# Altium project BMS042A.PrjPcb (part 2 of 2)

## Sheet BMS042A_SCH_Hardware.SchDoc
size 431 x 279 mm; Date: Not shown in title block; ApprovedBy: Not shown in title block; CheckedBy: Not shown in title block; Author: Not shown in title block; CompanyName: Not shown in title block; DrawnBy: Pengzhao Zhu; Engineer: Not shown in title block; Organization: Not shown in title block; Address1: Not shown in title block; Address2: Not shown in title block; Address3: Not shown in title block; Address4: Not shown in title block; DocumentNumber: 4; Revision: Use project parameter SCH_Rev; SheetNumber: 4; SheetTotal: 4; PageSetup: Record=PageOptions¦CenterHorizontal=True¦CenterVertical=True¦PrintScale=1.00¦XCorrection=1.00¦YCorrection=1.00¦PrintKind=0¦BorderSize=5000000¦LeftOffset=0¦BottomOffset=0¦Orientation=2¦PaperLength=1000¦PaperWidth=1000¦Scale=100¦PaperSource=15¦PrintQuality=600¦MediaType=1¦DitherType=10¦PaperKind=Letter¦PrintScaleMode=1
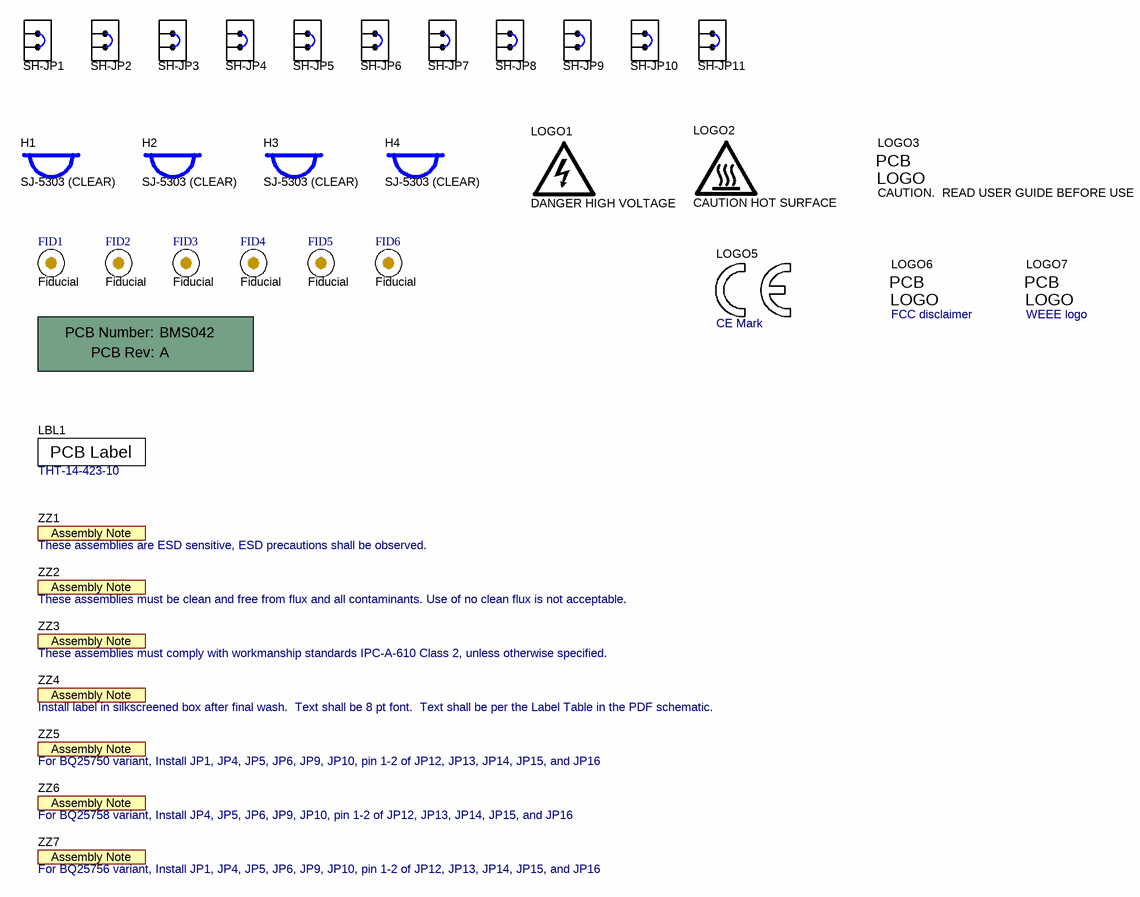
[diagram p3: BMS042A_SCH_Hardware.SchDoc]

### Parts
FID1  Fiducial  [Fiducial10-20]
FID2  Fiducial  [Fiducial10-20]
FID3  Fiducial  [Fiducial10-20]
FID4  Fiducial  [Fiducial10-20]
FID5  Fiducial  [Fiducial10-20]
FID6  Fiducial  [Fiducial10-20]
H1  SJ-5303 (CLEAR)  [Bumpon_SJ5003Transparent]
H2  SJ-5303 (CLEAR)  [Bumpon_SJ5003Transparent]
H3  SJ-5303 (CLEAR)  [Bumpon_SJ5003Transparent]
H4  SJ-5303 (CLEAR)  [Bumpon_SJ5003Transparent]
LBL1  THT-14-423-10  [Label_650x200]
LOGO1  DANGER HIGH VOLTAGE  [IEC_HighVoltage_Small]  (no BOM)
LOGO2  CAUTION HOT SURFACE  [IEC_HotSurface_Medium]  (no BOM)
LOGO3  CAUTION.  READ USER GUIDE BEFORE USE  [IEC_Caution_Medium]  (no BOM)
LOGO5  CE Mark  [CE_Mark_5mm]  (no BOM)
LOGO6  FCC disclaimer  [FCC_disclaimer]  (no BOM)
LOGO7  WEEE logo  [WEEE_Minimum]  (no BOM)
PCB1  Printed Circuit Board  (value not drawn)  (mechanical)
SH-JP1  SNT-100-BK-G  [SNT-100-BK-G]  (value not drawn)
SH-JP2  SNT-100-BK-G  [SNT-100-BK-G]  (value not drawn)
SH-JP3  SNT-100-BK-G  [SNT-100-BK-G]  (value not drawn)
SH-JP4  SNT-100-BK-G  [SNT-100-BK-G]  (value not drawn)
SH-JP5  SNT-100-BK-G  [SNT-100-BK-G]  (value not drawn)
SH-JP6  SNT-100-BK-G  [SNT-100-BK-G]  (value not drawn)
SH-JP7  SNT-100-BK-G  [SNT-100-BK-G]  (value not drawn)
SH-JP8  SNT-100-BK-G  [SNT-100-BK-G]  (value not drawn)
SH-JP9  SNT-100-BK-G  [SNT-100-BK-G]  (value not drawn)
SH-JP10  SNT-100-BK-G  [SNT-100-BK-G]  (value not drawn)
SH-JP11  SNT-100-BK-G  [SNT-100-BK-G]  (value not drawn)
ZZ1  These assemblies are ESD sensitive, ESD precautions shall be observed.  [AssemblyNote]  (no BOM)
ZZ2  These assemblies must be clean and free from flux and all contaminants. Use of no clean flux is not acceptable.  [AssemblyNote]  (no BOM)
ZZ3  These assemblies must comply with workmanship standards IPC-A-610 Class 2, unless otherwise specified.  [AssemblyNote]  (no BOM)
ZZ4  Install label in silkscreened box after final wash.  Text shall be 8 pt font.  Text shall be per the Label Table in the PDF schematic.  [AssemblyNote]  (no BOM)
ZZ5  For BQ25750 variant, Install JP1, JP4, JP5, JP6, JP9, JP10, pin 1-2 of JP12, JP13, JP14, JP15, and JP16  [AssemblyNote]  (no BOM)
ZZ6  For BQ25758 variant, Install JP4, JP5, JP6, JP9, JP10, pin 1-2 of JP12, JP13, JP14, JP15, and JP16  [AssemblyNote]  (no BOM)
ZZ7  For BQ25756 variant, Install JP1, JP4, JP5, JP6, JP9, JP10, pin 1-2 of JP12, JP13, JP14, JP15, and JP16  [AssemblyNote]  (no BOM)

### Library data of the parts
FID1-FID6 = CMP-0077181-1: Fiducial mark.  There is nothing to buy or mount.
H1-H4 = CMP-0003620-1: Bumpon, Hemisphere, 0.44 X 0.20, Clear; Manufacturer: 3M
LBL1 = CMP-0003625-1: Thermal Transfer Printable Labels, 0.650" W x 0.200" H - 10,000 per roll; Manufacturer: Brady; Note: Size: 0.65" x 0.20 "
LOGO1 = CMP-0074835-1: IEC 61010-1 High Voltage Warning; SymbolCreator: a0412235
LOGO2 = CMP-0074837-2: IEC 61010-1 Hot Surface Warning; Manufacturer: Texas Instruments; CompType: IC; AEC Category: Q200; SymbolCreator: a0412235
LOGO3 = CMP-0074836-1: IEC 61010-1 Caution Warning; SymbolCreator: a0412235; Lib Reference: IEC_Caution
LOGO5 = CMP-0074844-1: SymbolCreator: a0412235
LOGO6 = CMP-0074847-1: FCC_disclaimer
LOGO7 = CMP-0074769-1
PCB1 = CMP-0003618-2: Manufacturer: Any; PartNumber: BMS042
SH-JP1-SH-JP11 = CMP-0003623-3: Shunt, 100mil, Gold plated, Black; Manufacturer: Samtec; Alternate Manufacturer: 3M; Alternate PartNumber: 969102-0000-DA; Value: 1x2; Note: You can "mate" this to a header by matching the designator.  i.e. use SH-J3 for header J3
ZZ1 = CMP-0077236-1
ZZ2 = CMP-0077237-1
ZZ3 = CMP-0077238-1
ZZ4-ZZ7 = CMP-0077238-1: These assemblies must comply with workmanship standards IPC-A-610 Class 2, unless otherwise specified.

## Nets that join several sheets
PGND: BMS042A_SCH_page1 (41 pins), BMS042A_SCH_page2 (34 pins), BMS042A_SCH_powerpath_capacitors (50 pins)
/CE: BMS042A_SCH_page1 (U1.7), BMS042A_SCH_page2 (JP13.1 R56.1 TP21.1)
/INT: BMS042A_SCH_page1 (U1.3), BMS042A_SCH_page2 (J8.5 JP14.2 TP30.1)
/PG: BMS042A_SCH_page1 (U1.6), BMS042A_SCH_page2 (D6.1 J8.8 TP9.1)
AC_OUT: BMS042A_SCH_page1 (8 pins), BMS042A_SCH_powerpath_capacitors (6 pins)
ACDRV: BMS042A_SCH_page1 (R12.1 U1.31), BMS042A_SCH_page2 (TP4.1)
ACN: BMS042A_SCH_page1 (C11.1 C34.2 R6.1 U1.29), BMS042A_SCH_page2 (TP11.1)
ACOV: BMS042A_SCH_page1 (C32.1 R27.1 R30.2 U1.35), BMS042A_SCH_page2 (TP14.1)
ACP: BMS042A_SCH_page1 (C10.1 C34.1 R5.1 U1.30), BMS042A_SCH_page2 (TP10.1)
ACUV: BMS042A_SCH_page1 (C20.1 R21.1 R27.2 U1.34), BMS042A_SCH_page2 (TP13.1)
BAT: BMS042A_SCH_page1 (7 pins), BMS042A_SCH_page2 (D9.2 J7.1 TP3.1), BMS042A_SCH_powerpath_capacitors (11 pins)
BAT_DRV: BMS042A_SCH_page1 (R9.2 U1.15), BMS042A_SCH_page2 (TP5.1)
BAT_SRC: BMS042A_SCH_page1 (10 pins), BMS042A_SCH_page2 (TP6.1)
BTST1: BMS042A_SCH_page1 (R13.1 U1.26), BMS042A_SCH_page2 (TP26.1)
BTST2: BMS042A_SCH_page1 (R23.1 U1.20), BMS042A_SCH_page2 (TP28.1)
DRV_SUP: BMS042A_SCH_page1 (C26.1 R120.2 U1.23), BMS042A_SCH_page2 (JP12.2 R300.2 TP15.1)
FB: BMS042A_SCH_page1 (5 pins), BMS042A_SCH_page2 (TP24.1)
FBG: BMS042A_SCH_page1 (JP2.2 R64.1 U1.11), BMS042A_SCH_page2 (TP42.1)
FSW_SYNC: BMS042A_SCH_page1 (U1.36), BMS042A_SCH_page2 (JP8.1 R36.2 TP16.1)
HIDRV1: BMS042A_SCH_page1 (R8.2 U1.27), BMS042A_SCH_page2 (TP25.1)
HIDRV2: BMS042A_SCH_page1 (R3.2 U1.19), BMS042A_SCH_page2 (TP27.1)
ICHG: BMS042A_SCH_page1 (U1.9), BMS042A_SCH_page2 (JP3.1 R67.2 R201.2 TP17.1)
ILIM_HIZ: BMS042A_SCH_page1 (U1.10), BMS042A_SCH_page2 (JP11.1 R66.2 R200.2 TP7.1)
LODRV1: BMS042A_SCH_page1 (R20.1 U1.25), BMS042A_SCH_page2 (TP43.1)
LODRV2: BMS042A_SCH_page1 (R17.1 U1.21), BMS042A_SCH_page2 (TP44.1)
MODE: BMS042A_SCH_page1 (R32.2 U1.17), BMS042A_SCH_page2 (TP20.1)
P_OUT: BMS042A_SCH_page1 (11 pins), BMS042A_SCH_powerpath_capacitors (15 pins)
REGN: BMS042A_SCH_page1 (C22.1 U1.24), BMS042A_SCH_page2 (JP5.1 R160.1 TP1.1)
SCL: BMS042A_SCH_page1 (U1.1), BMS042A_SCH_page2 (5 pins)
SDA: BMS042A_SCH_page1 (U1.2), BMS042A_SCH_page2 (5 pins)
SRN: BMS042A_SCH_page1 (C23.1 C35.2 R25.2 U1.13), BMS042A_SCH_page2 (TP23.1)
SRP: BMS042A_SCH_page1 (C21.1 C35.1 R22.2 U1.14), BMS042A_SCH_page2 (TP22.1)
STAT1: BMS042A_SCH_page1 (U1.4), BMS042A_SCH_page2 (JP15.2 TP29.1)
STAT2: BMS042A_SCH_page1 (U1.5), BMS042A_SCH_page2 (D5.1 TP31.1)
SW1: BMS042A_SCH_page1 (10 pins), BMS042A_SCH_page2 (TP18.1)
SW2: BMS042A_SCH_page1 (13 pins), BMS042A_SCH_page2 (TP19.1)
SYS: BMS042A_SCH_page1 (5 pins), BMS042A_SCH_page2 (TP2.1)
TS: BMS042A_SCH_page1 (U1.8), BMS042A_SCH_page2 (5 pins)
VAC: BMS042A_SCH_page1 (12 pins), BMS042A_SCH_page2 (D10.2 J7.4 J7.5 TP12.1)
VSYS: BMS042A_SCH_page1 (11 pins), BMS042A_SCH_powerpath_capacitors (18 pins)

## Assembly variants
BQ25756: not fitted C3 C6 C9 C14 C15 C20 C25 C32 C36 C45 C46 C49 C54 C60 C63 C74 C77 C151 C200 C500 C501 C502 C503 C504 C505 C506 C507 C508 C509 C510 C511 C512 C513 C514 C515 C516 C517 C518 C519 D1 D7 D8 J2 L2 Q5 Q6 Q7 Q8 R9 R12 R14 R15 R59 R100 R151 R152 R153 R154 R300 R400 R401 R1002 R1003 R1004 R1005; alternate parts U1 -> CMP-0093460-1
